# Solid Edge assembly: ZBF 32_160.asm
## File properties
Title: Zylinder
Author: bmolnar
Template: iso metric assembly.asm
Last saved by: bmolnar
Revision: 28
Application: Solid Edge
Username: bmolnar
Dokumentum tartalom típus: 1
Document Number: ZBF 32/160
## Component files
Profilrohr.par
Kolbenstange.par
Kit.par
Mutter.par
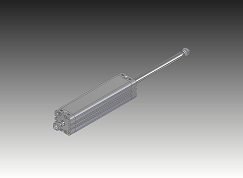
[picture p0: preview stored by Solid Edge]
